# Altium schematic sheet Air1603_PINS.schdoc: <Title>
size 419 x 266 mm; Name: SIZEB; Symbol: SIZEB; Device: SIZEB; Drawn By: <Drawn By>; Checked By: <Checked By>; QC By: <QC By>; Released By: <Released By>; Drawn Date: <Drawn Date>; Checked Date: <Checked Date>; QC Date: <QC Date>; Release Date: <Release Date>; Company Name: <Company Name>; Code: <Code>; Sheet Size: B; Drawing Number: <Drawing Number>; Revision: <Revision>; Scale: <Scale>; Sheet Number: 1; Number of Sheets: 1
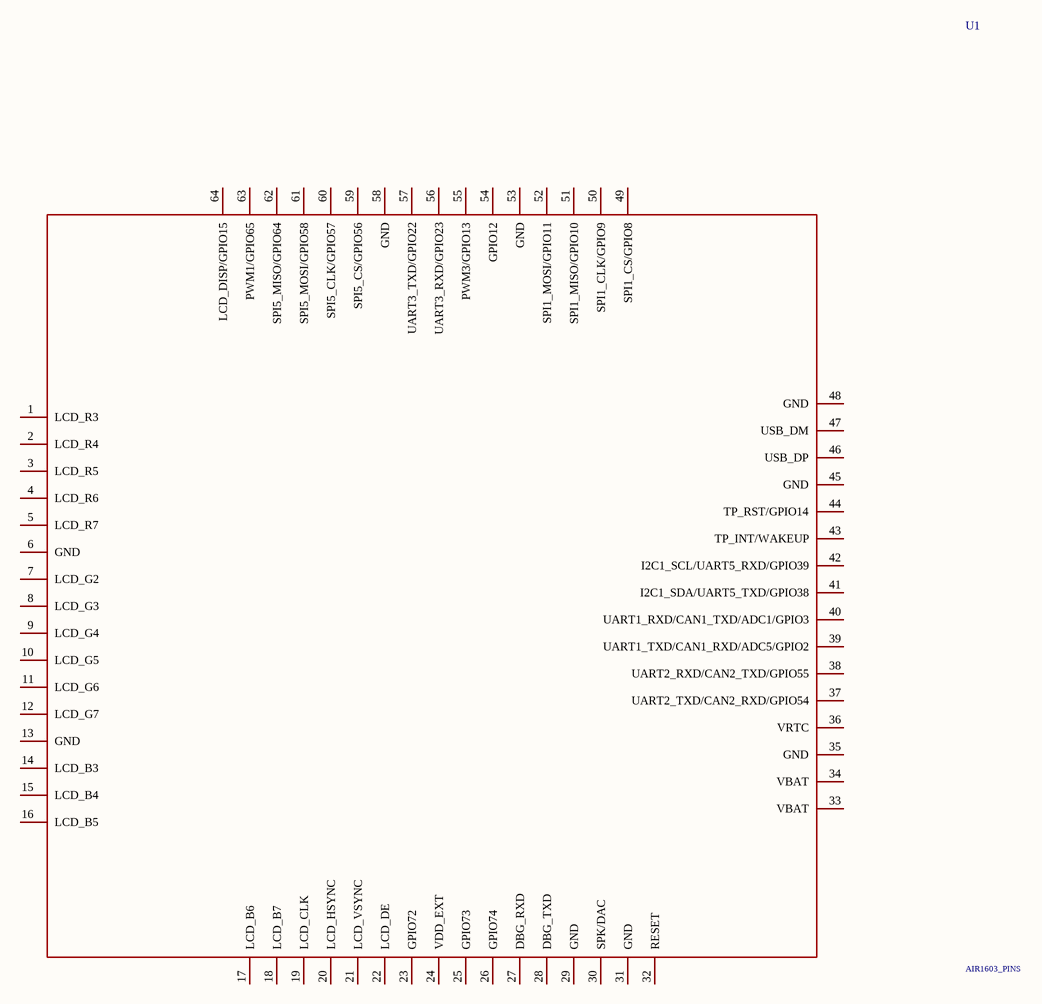
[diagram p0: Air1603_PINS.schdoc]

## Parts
U1  AIR1603_PINS

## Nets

Not connected (* = marked no-connect by the designer): U1 1(LCD_R3) 2(LCD_R4) 3(LCD_R5) 4(LCD_R6) 5(LCD_R7) 6(GND) 7(LCD_G2) 8(LCD_G3) 9(LCD_G4) 10(LCD_G5) 11(LCD_G6) 12(LCD_G7) 13(GND) 14(LCD_B3) 15(LCD_B4) 16(LCD_B5) 17(LCD_B6) 18(LCD_B7) 19(LCD_CLK) 20(LCD_HSYNC) 21(LCD_VSYNC) 22(LCD_DE) 23(GPIO72) 24(VDD_EXT) 25(GPIO73) 26(GPIO74) 27(DBG_RXD) 28(DBG_TXD) 29(GND) 30(SPK/DAC) 31(GND) 32(RESET) 33(VBAT) 34(VBAT) 35(GND) 36(VRTC) 37(UART2_TXD/CAN2_RXD/GPIO54) 38(UART2_RXD/CAN2_TXD/GPIO55) 39(UART1_TXD/CAN1_RXD/ADC5/GPIO2) 40(UART1_RXD/CAN1_TXD/ADC1/GPIO3) 41(I2C1_SDA/UART5_TXD/GPIO38) 42(I2C1_SCL/UART5_RXD/GPIO39) 43(TP_INT/WAKEUP) 44(TP_RST/GPIO14) 45(GND) 46(USB_DP) 47(USB_DM) 48(GND) 49(SPI1_CS/GPIO8) 50(SPI1_CLK/GPIO9) 51(SPI1_MISO/GPIO10) 52(SPI1_MOSI/GPIO11) 53(GND) 54(GPIO12) 55(PWM3/GPIO13) 56(UART3_RXD/GPIO23) 57(UART3_TXD/GPIO22) 58(GND) 59(SPI5_CS/GPIO56) 60(SPI5_CLK/GPIO57) 61(SPI5_MOSI/GPIO58) 62(SPI5_MISO/GPIO64) 63(PWM1/GPIO65) 64(LCD_DISP/GPIO15)

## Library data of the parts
U1 = AIR1603_PINS: Add into BOM: yes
